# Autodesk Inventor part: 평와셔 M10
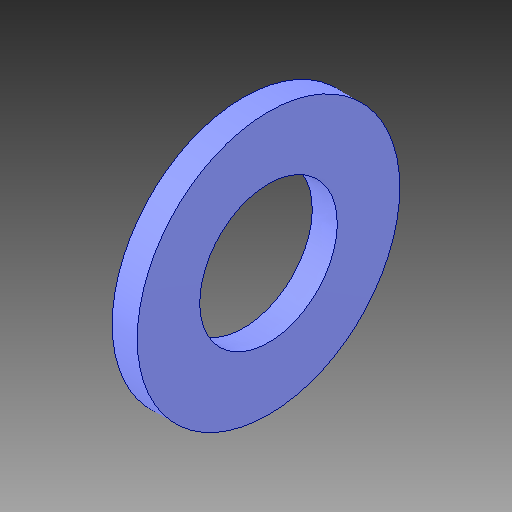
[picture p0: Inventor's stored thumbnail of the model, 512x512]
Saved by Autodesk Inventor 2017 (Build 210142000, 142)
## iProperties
Created: 2024-08
Part Number: 평와셔 M10
Material: 일반
Description: 평면 와셔
Document SubType Name: Modeling
Designer: MRC
Density: 1 g/cm^3
Appearance: 기본값
Author: jhkim
Sending System: Autodesk Inventor 2025
Preprocessor: ST-DEVELOPER v20
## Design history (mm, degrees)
feature "Solid1"
node "솔리드1"
